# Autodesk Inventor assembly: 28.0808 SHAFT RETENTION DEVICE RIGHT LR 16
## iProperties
Created: 2009-01
Part Number: 28.0808 SHAFT RETENTION DEVICE RIGHT LR 16
Document SubType Name: Assembly
Designer: Administrator
Author: Administrator
